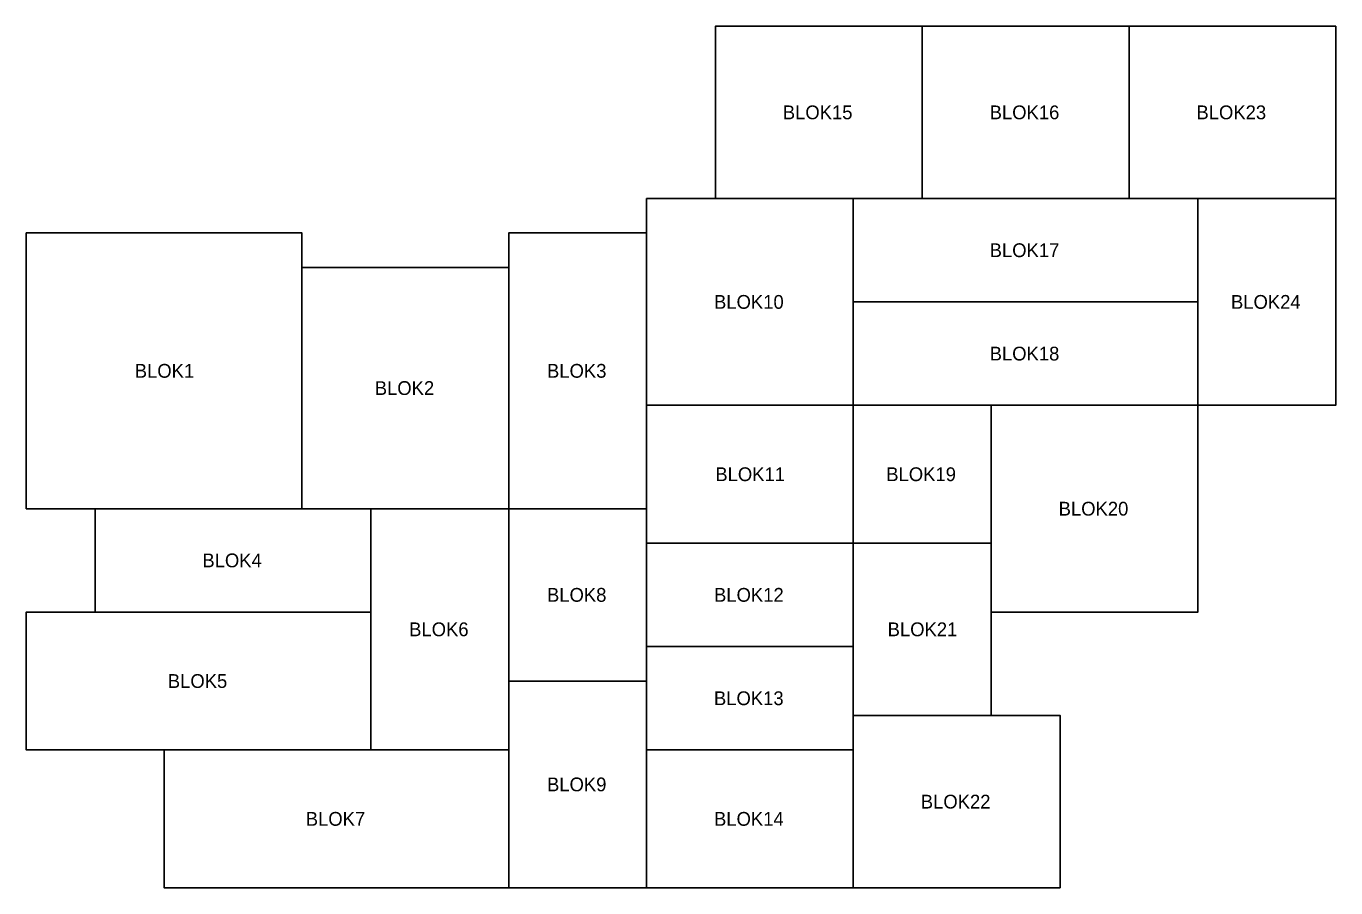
# Model space of a CAD drawing. Extents: x 124000 to 143000, y 393500 to 406000.
import ezdxf

# ---------------------------------------------------------------- set-up
doc = ezdxf.new("R2010")
doc.units = 0
for name, color, linetype in [('Blok1', 7, 'Continuous'), ('Blok2', 7, 'Continuous'), ('Blok3', 7, 'Continuous'), ('Default', 7, 'Continuous')]:
    doc.layers.add(name, color=color, linetype=linetype)

msp = doc.modelspace()

# ---------------------------------------------------------------- linework, layer by layer
at = {"layer": 'Blok1'}
msp.add_lwpolyline([(124000, 403000), (128000, 403000), (128000, 402500), (131000, 402500), (131000, 403000), (133000, 403000), (133000, 399000), (131000, 399000), (131000, 393500), (126000, 393500), (126000, 395500), (124000, 395500), (124000, 397500), (125000, 397500), (125000, 399000), (124000, 399000)], close=True, dxfattribs=at)
at = {"layer": 'Blok2'}
msp.add_lwpolyline([(131000, 399000), (131000, 393500), (136000, 393500), (136000, 403500), (133000, 403500), (133000, 399000)], close=True, dxfattribs=at)
at = {"layer": 'Blok3'}
msp.add_lwpolyline([(134000, 403500), (134000, 406000), (143000, 406000), (143000, 400500), (141000, 400500), (141000, 397500), (138000, 397500), (138000, 396000), (139000, 396000), (139000, 393500), (136000, 393500), (136000, 403500)], close=True, dxfattribs=at)
at = {"layer": 'Default'}
for points in [[(134000, 403500), (137000, 403500), (137000, 406000), (134000, 406000)], [(137000, 406000), (140000, 406000), (140000, 403500), (137000, 403500)], [(140000, 406000), (143000, 406000), (143000, 403500), (140000, 403500)], [(133000, 403500), (136000, 403500), (136000, 400500), (133000, 400500)], [(136000, 403500), (141000, 403500), (141000, 402000), (136000, 402000)], [(141000, 403500), (143000, 403500), (143000, 400500), (141000, 400500)], [(124000, 403000), (128000, 403000), (128000, 399000), (124000, 399000)], [(131000, 403000), (133000, 403000), (133000, 399000), (131000, 399000)], [(128000, 402500), (131000, 402500), (131000, 399000), (128000, 399000)], [(136000, 402000), (141000, 402000), (141000, 400500), (136000, 400500)], [(133000, 400500), (136000, 400500), (136000, 398500), (133000, 398500)], [(136000, 400500), (138000, 400500), (138000, 398500), (136000, 398500)], [(141000, 400500), (138000, 400500), (138000, 397500), (141000, 397500)], [(125000, 399000), (129000, 399000), (129000, 397500), (125000, 397500)], [(129000, 399000), (131000, 399000), (131000, 395500), (129000, 395500)], [(131000, 399000), (133000, 399000), (133000, 396500), (131000, 396500)], [(136000, 398500), (133000, 398500), (133000, 397000), (136000, 397000)], [(136000, 396000), (138000, 396000), (138000, 398500), (136000, 398500)], [(124000, 397500), (129000, 397500), (129000, 395500), (124000, 395500)], [(133000, 397000), (136000, 397000), (136000, 395500), (133000, 395500)], [(131000, 393500), (133000, 393500), (133000, 396500), (131000, 396500)], [(136000, 393500), (139000, 393500), (139000, 396000), (136000, 396000)], [(126000, 395500), (131000, 395500), (131000, 393500), (126000, 393500)], [(133000, 395500), (136000, 395500), (136000, 393500), (133000, 393500)]]:
    msp.add_lwpolyline(points, close=True, dxfattribs=at)

# ---------------------------------------------------------------- texts
for s, p in [('BLOK15', (134977, 404650)), ('BLOK16', (137978, 404650)), ('BLOK23', (140978, 404650)), ('BLOK17', (137978, 402650)), ('BLOK10', (133979, 401900)), ('BLOK24', (141479, 401900)), ('BLOK18', (137978, 401150)), ('BLOK1', (125575, 400900)), ('BLOK3', (131556, 400900)), ('BLOK2', (129057, 400650)), ('BLOK11', (133998, 399400)), ('BLOK19', (136478, 399400)), ('BLOK20', (138979, 398900)), ('BLOK4', (126556, 398150)), ('BLOK8', (131556, 397650)), ('BLOK12', (133979, 397650)), ('BLOK6', (129556, 397150)), ('BLOK21', (136498, 397150)), ('BLOK5', (126055, 396400)), ('BLOK13', (133978, 396150)), ('BLOK9', (131556, 394900)), ('BLOK22', (136979, 394650)), ('BLOK7', (128056, 394400)), ('BLOK14', (133979, 394400))]:
    msp.add_text(s, height=200, dxfattribs=at).set_placement(p)

doc.saveas('drawing.dxf')
